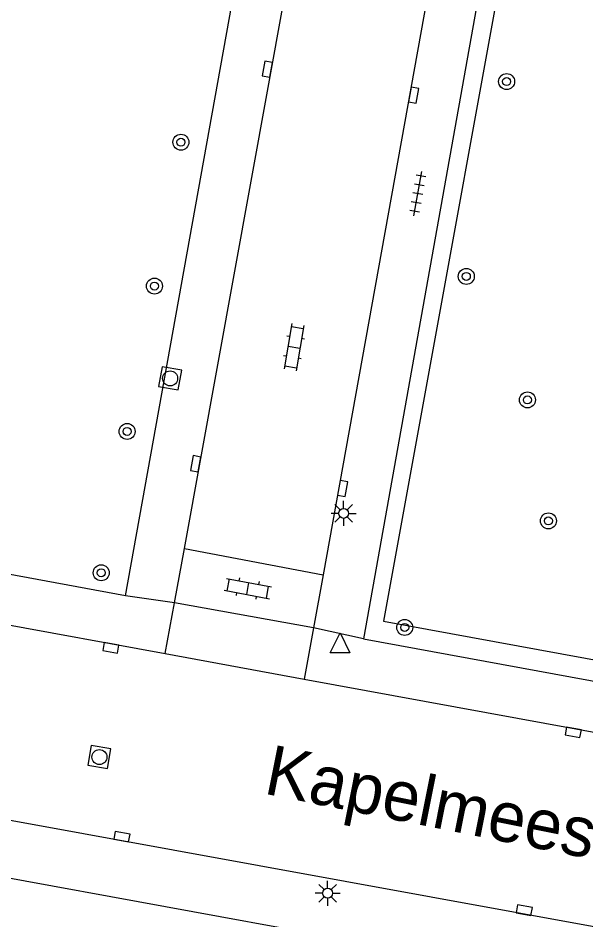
# Model space of a CAD drawing. Extents: x 133000 to 136000, y 400500 to 403500.
# Drawn here: x 133410.31 to 133438.72, y 400611.88 to 400657 of the extents above; entities that cross this region are included whole.
import ezdxf

# ---------------------------------------------------------------- set-up
doc = ezdxf.new("R2010")
doc.units = 0
for name, color, linetype in [('gg-anno-openbare ruimte label', 7, 'Continuous'), ('gg-knt-verharding', 7, 'Continuous'), ('gt-grn-groengrens', 7, 'Continuous'), ('gt-grn-weggrens', 7, 'Continuous'), ('gt-symb-boom', 7, 'Continuous'), ('gt-symb-klinker verharding', 7, 'Continuous'), ('gt-symb-kolk', 7, 'Continuous'), ('gt-symb-lichtmast', 7, 'Continuous'), ('gt-symb-rioolschacht', 7, 'Continuous'), ('gt-symb-tegel verharding', 7, 'Continuous'), ('gt-symb-waterafsluiter', 7, 'Continuous')]:
    doc.layers.add(name, color=color, linetype=linetype)

# ---------------------------------------------------------------- blocks, each defined once
blk = doc.blocks.new('gt0-KL1')
at = {"layer": 'gt-symb-klinker verharding'}
for p, q in [((-1.15, 0.3), (1.15, 0.3)), ((-1, -0.3), (-1, 0.3)), ((-0.5, 0.3), (-0.5, 0.45)), ((0, -0.3), (0, 0.3)), ((0.5, 0.3), (0.5, 0.45)), ((1, -0.3), (1, 0.3)), ((-1.15, -0.3), (1.15, -0.3)), ((-0.5, -0.45), (-0.5, -0.3)), ((0.5, -0.45), (0.5, -0.3))]:
    blk.add_line(p, q, dxfattribs=at)
blk = doc.blocks.new('gt0-BOOM')
at = {"layer": 'gt-symb-boom'}
for radius in [0.4, 0.2]:
    blk.add_circle((0, 0), radius, dxfattribs=at)
blk = doc.blocks.new('gt0-KOLK')
at = {"layer": 'gt-symb-kolk'}
blk.add_lwpolyline([(0, 0), (0.375, 0), (0.375, 0.4), (-0.375, 0.4), (-0.375, 0), (0, 0)], dxfattribs=at)
blk = doc.blocks.new('gt0-WAFSL')
at = {"layer": 'gt-symb-waterafsluiter'}
for p, q in [((-0.5, -0.333), (0, 0.667)), ((0, 0.667), (0.5, -0.333)), ((0.5, -0.333), (-0.5, -0.333))]:
    blk.add_line(p, q, dxfattribs=at)
blk = doc.blocks.new('gt0-RS')
at = {"layer": 'gt-symb-rioolschacht'}
blk.add_lwpolyline([(-0.5, -0.5), (0.5, -0.5), (0.5, 0.5), (-0.5, 0.5)], close=True, dxfattribs=at)
blk.add_circle((0, 0), 0.375, dxfattribs=at)
blk = doc.blocks.new('gt0-TEG1')
at = {"layer": 'gt-symb-tegel verharding'}
for p, q in [((-1.125, 0), (1.125, 0)), ((-0.9, -0.25), (-0.9, 0.25)), ((-0.45, -0.25), (-0.45, 0.25)), ((0, -0.25), (0, 0.25)), ((0.45, -0.25), (0.45, 0.25)), ((0.9, -0.25), (0.9, 0.25))]:
    blk.add_line(p, q, dxfattribs=at)
blk = doc.blocks.new('gt0-LMAST')
at = {"layer": 'gt-symb-lichtmast'}
for p, q in [((-0.005, 0.246), (-0.005, 0.621)), ((-0.182, 0.173), (-0.447, 0.438)), ((0.172, 0.173), (0.437, 0.438)), ((-0.255, -0.004), (-0.63, -0.004)), ((-0.182, -0.181), (-0.447, -0.446)), ((-0.005, -0.254), (-0.005, -0.629)), ((0.437, -0.446), (0.172, -0.181)), ((0.245, -0.004), (0.62, -0.004))]:
    blk.add_line(p, q, dxfattribs=at)
blk.add_circle((-0.005, -0.004), 0.25, dxfattribs=at)

msp = doc.modelspace()

# ---------------------------------------------------------------- linework, layer by layer
at = {"layer": 'gg-knt-verharding'}
for p, q in [((133435.85, 400672.1), (133427.59, 400625.95)), ((133418.634, 400630.474), (133425.109, 400666.169)), ((133432.015, 400664.87), (133425.57, 400629.157)), ((133415.69, 400628.1), (133390.638, 400632.693)), ((133390.187, 400630.235), (133417.675, 400625.209)), ((133418.14, 400627.75), (133418.634, 400630.474)), ((133418.634, 400630.474), (133425.57, 400629.157)), ((133425.57, 400629.157), (133425.09, 400626.5)), ((133425.09, 400626.5), (133418.14, 400627.75)), ((133427.59, 400625.95), (133452.759, 400621.338)), ((133417.675, 400625.209), (133424.622, 400623.938)), ((133424.622, 400623.938), (133452.377, 400618.863)), ((133450.637, 400609.434), (133398.171, 400619.01)), ((133426.075, 400611.005), (133397.66, 400616.21))]:
    msp.add_line(p, q, dxfattribs=at)
msp.add_lwpolyline([(133415.69, 400628.1), (133421.28, 400659.26), (133419.42, 400659.52)], dxfattribs=at)
at = {"layer": 'gt-grn-groengrens'}
msp.add_lwpolyline([(133436.676, 400671.34), (133428.589, 400626.834), (133457.551, 400621.532)], dxfattribs=at)
at = {"layer": 'gt-grn-weggrens'}
for p, q in [((133418.14, 400627.75), (133415.69, 400628.1)), ((133417.675, 400625.209), (133418.14, 400627.75)), ((133425.09, 400626.5), (133424.622, 400623.938)), ((133427.59, 400625.95), (133425.09, 400626.5))]:
    msp.add_line(p, q, dxfattribs=at)

# ---------------------------------------------------------------- block references
at = {"layer": 'gt-symb-boom'}
for p in [(133434.753, 400653.828), (133418.457, 400650.794), (133432.735, 400644.078), (133417.133, 400643.595), (133435.795, 400637.9), (133415.765, 400636.323), (133436.843, 400631.85), (133414.467, 400629.253), (133429.652, 400626.516)]:
    msp.add_blockref('gt0-BOOM', p, dxfattribs=at)
at = {"layer": 'gt-symb-klinker verharding'}
for p, rotation in [((133424.113, 400640.544), -99.44347491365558), ((133421.805, 400628.464), -10.714643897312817)]:
    msp.add_blockref('gt0-KL1', p, dxfattribs=dict(at, rotation=rotation))
at = {"layer": 'gt-symb-kolk'}
for p, rotation in [((133422.976, 400654.415), 79.80279442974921), ((133429.905, 400653.185), -100.19720557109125), ((133419.392, 400634.674), 79.74640197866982), ((133426.35, 400633.501), -100.19720557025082), ((133414.987, 400625.7), 169.74640197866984), ((133438.122, 400621.469), 169.69002960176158), ((133415.47, 400615.854), -10.366322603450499), ((133435.601, 400612.176), -10.309970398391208)]:
    msp.add_blockref('gt0-KOLK', p, dxfattribs=dict(at, rotation=rotation))
at = {"layer": 'gt-symb-lichtmast'}
for p in [(133426.603, 400632.23), (133425.802, 400613.228)]:
    msp.add_blockref('gt0-LMAST', p, dxfattribs=at)
at = {"layer": 'gt-symb-rioolschacht'}
for p, rotation in [((133417.917, 400638.977), 80.03848340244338), ((133414.378, 400620.034), 170.62242087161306)]:
    msp.add_blockref('gt0-RS', p, dxfattribs=dict(at, rotation=rotation))
at = {"layer": 'gt-symb-tegel verharding', "rotation": 79.85920685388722}
msp.add_blockref('gt0-TEG1', (133430.307, 400648.215), dxfattribs=at)
at = {"layer": 'gt-symb-waterafsluiter'}
msp.add_blockref('gt0-WAFSL', (133426.415, 400625.586), dxfattribs=at)

# ---------------------------------------------------------------- texts
at = {"layer": 'gg-anno-openbare ruimte label'}
msp.add_text('Kapelmeesterlaan', height=2.5, rotation=348.7, dxfattribs=at).set_placement((133422.542, 400618.218))

doc.saveas('drawing.dxf')
